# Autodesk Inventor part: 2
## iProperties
Created: 2012-03
Part Number: 2
Document SubType Name: Modeling
Designer: Administrator
Density: 7.85 g/cm^3
Material: Steel
Mass: 48.3252 g
Surface Area: 74.8646 cm^2
Volume: 6.15608 cm^3
Translation Standard: STEP AP203
FileName: //expscmdclustefs.cadenas.external/client_exchange/iodir/jobs/output/wkb42693478_no0/STEP/208_9001__24208_90010__2_03.stp
PostProcessor: Build: 236a, Release: 2009 RTM - Date: Fri 02/22/2008
Sent Units: CM
Uncertainty: 0.0
Author: Administrator
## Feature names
1. Base1
